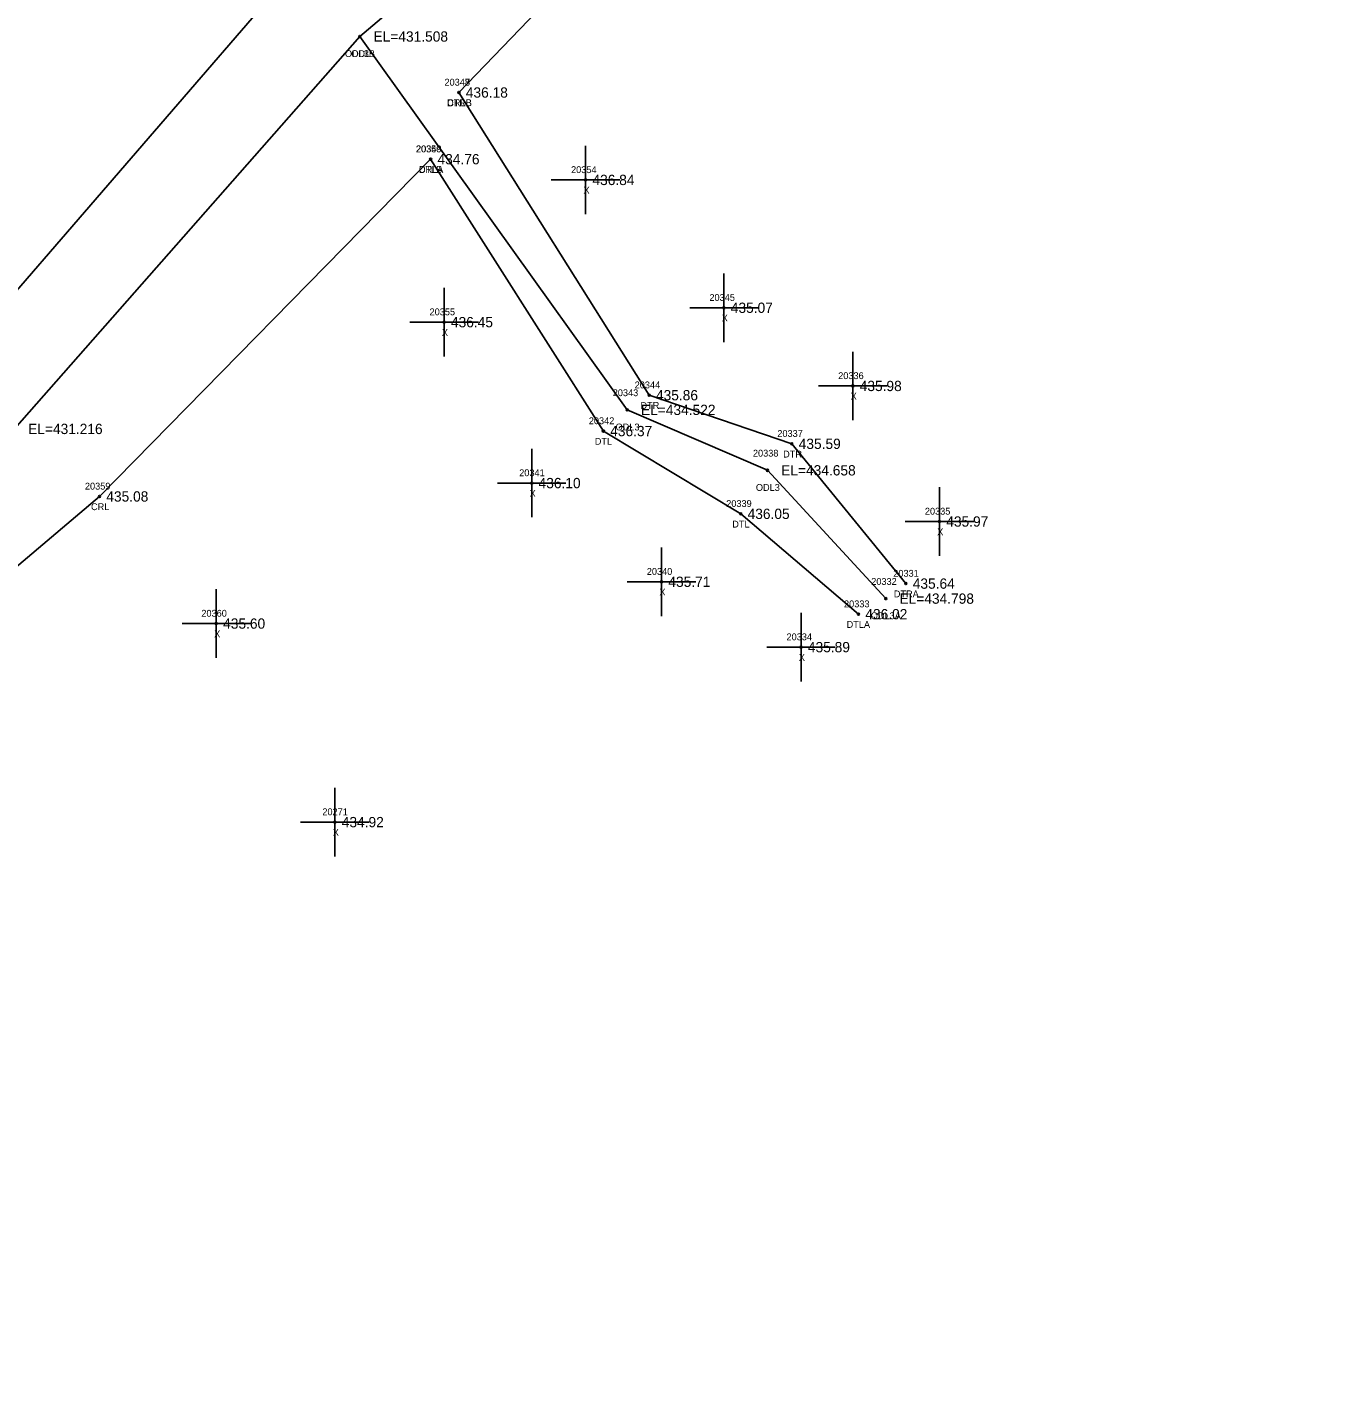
# Model space of a CAD drawing. Extents: x 1797709 to 1799052, y 896018 to 896955.
# Drawn here: x 1798186.8 to 1798378.7, y 896130.7 to 896328.3 of the extents above; entities that cross this region are included whole.
import ezdxf

# ---------------------------------------------------------------- set-up
doc = ezdxf.new("R2010")
doc.units = 0
for name, color, linetype in [('RD_EX_H2O', 7, 'Continuous'), ('RD_EX_H2O_txCode', 7, 'Continuous'), ('RD_EX_Misc', 7, 'Continuous'), ('RD_EX_Misc_txCode', 7, 'Continuous'), ('RD_EX_TX_H2O_ELEV', 7, 'Continuous'), ('RD_EX_TX_Misc_ELEV', 7, 'Continuous'), ('RD_SMD_Locator', 7, 'Continuous')]:
    doc.layers.add(name, color=color, linetype=linetype)

msp = doc.modelspace()

# ---------------------------------------------------------------- linework, layer by layer
at = {"layer": 'RD_EX_H2O'}
for points in [[(1798652.43, 896917.58), (1798601.94, 896827.15), (1798558.78, 896718.92), (1798516.66, 896628.32), (1798463.08, 896540.21), (1798439.21, 896521.86), (1798389.85, 896497.35), (1798369.72, 896471.55), (1798343.52, 896433.35), (1798291.39, 896374.31), (1798235.39, 896326.89), (1798184.99, 896269.63), (1798095.18, 896198.01), (1798023.89, 896139.85)], [(1798502.61, 896635.66), (1798452.16, 896551.79), (1798380.86, 896504.02), (1798360.17, 896479.84), (1798335.44, 896438.68), (1798277.37, 896387.2), (1798228.36, 896339.61), (1798175.66, 896278.7), (1798083.83, 896204.11), (1798020.11, 896146.19)], [(1798443.56, 896510.19), (1798406.44, 896491.18), (1798387.57, 896460.96), (1798358.05, 896423.51), (1798298.17, 896368.97), (1798249.86, 896318.72)], [(1798312.14, 896244.87), (1798294.88, 896263.59), (1798274.42, 896272.41), (1798235.39, 896326.89)], [(1798315.08, 896247.06), (1798298.44, 896267.46), (1798277.61, 896274.55), (1798249.86, 896318.72)], [(1798245.73, 896308.99), (1798197.4, 896259.78), (1798112.74, 896188.08), (1798043.49, 896130.72)], [(1798308.16, 896242.6), (1798290.98, 896257.24), (1798270.93, 896269.32), (1798245.73, 896308.99)]]:
    msp.add_lwpolyline(points, dxfattribs=at)
at = {"layer": 'RD_EX_Misc'}
for p, q in [((1798268.34, 896300.96), (1798268.34, 896310.96)), ((1798263.34, 896305.96), (1798273.34, 896305.96)), ((1798288.53, 896282.31), (1798288.53, 896292.31)), ((1798247.69, 896280.21), (1798247.69, 896290.21)), ((1798283.53, 896287.31), (1798293.53, 896287.31)), ((1798242.69, 896285.21), (1798252.69, 896285.21)), ((1798307.34, 896270.9), (1798307.34, 896280.9)), ((1798302.34, 896275.9), (1798312.34, 896275.9)), ((1798260.48, 896256.73), (1798260.48, 896266.73)), ((1798255.48, 896261.73), (1798265.48, 896261.73)), ((1798319.97, 896251.12), (1798319.97, 896261.12)), ((1798314.97, 896256.12), (1798324.97, 896256.12)), ((1798279.42, 896242.33), (1798279.42, 896252.33)), ((1798214.45, 896236.23), (1798214.45, 896246.23)), ((1798274.42, 896247.33), (1798284.42, 896247.33)), ((1798299.78, 896232.79), (1798299.78, 896242.79)), ((1798209.45, 896241.23), (1798219.45, 896241.23)), ((1798294.78, 896237.79), (1798304.78, 896237.79)), ((1798231.76, 896207.26), (1798231.76, 896217.26)), ((1798226.76, 896212.26), (1798236.76, 896212.26))]:
    msp.add_line(p, q, dxfattribs=at)
at = {"layer": 'RD_SMD_Locator'}
for centre in [(1798235.39, 896326.89), (1798235.39, 896326.89), (1798249.86, 896318.72), (1798249.86, 896318.72), (1798245.73, 896308.99), (1798245.73, 896308.99), (1798268.34, 896305.96), (1798288.53, 896287.31), (1798247.69, 896285.21), (1798307.34, 896275.9), (1798277.61, 896274.55), (1798274.42, 896272.41), (1798270.93, 896269.32), (1798298.44, 896267.46), (1798294.88, 896263.59), (1798260.48, 896261.73), (1798197.4, 896259.78), (1798290.98, 896257.24), (1798319.97, 896256.12), (1798279.42, 896247.33), (1798315.08, 896247.06), (1798312.14, 896244.87), (1798308.16, 896242.6), (1798214.45, 896241.23), (1798299.78, 896237.79), (1798231.76, 896212.26)]:
    msp.add_circle(centre, 0.15, dxfattribs=at)

# ---------------------------------------------------------------- texts
at = {"layer": 'RD_EX_H2O_txCode'}
for s, p in [('ODL3B', (1798233.22, 896323.89)), ('ODL', (1798234.14, 896323.89)), ('20347', (1798247.75, 896319.72)), ('20348', (1798247.75, 896319.72)), ('CRLB', (1798248.16, 896316.72)), ('DTRB', (1798248.12, 896316.72)), ('20350', (1798243.57, 896309.99)), ('20349', (1798243.61, 896309.99)), ('CRLA', (1798244.01, 896306.99)), ('DTLB', (1798244.01, 896306.99)), ('20344', (1798275.5, 896275.55)), ('20343', (1798272.3, 896274.41)), ('DTR', (1798276.35, 896272.55)), ('20342', (1798268.81, 896270.32)), ('ODL3', (1798272.72, 896269.41)), ('DTL', (1798269.68, 896267.32)), ('20337', (1798296.32, 896268.46)), ('20338', (1798292.76, 896265.59)), ('DTR', (1798297.17, 896265.46)), ('20359', (1798195.28, 896260.78)), ('ODL3', (1798293.19, 896260.59)), ('CRL', (1798196.17, 896257.78)), ('20339', (1798288.86, 896258.24)), ('DTL', (1798289.74, 896255.24)), ('20332', (1798310.02, 896246.87)), ('20331', (1798313.24, 896248.06)), ('DTRA', (1798313.32, 896245.06)), ('20333', (1798306.05, 896243.6)), ('ODL3A', (1798309.96, 896241.87)), ('DTLA', (1798306.43, 896240.6))]:
    msp.add_text(s, height=1, dxfattribs=at).set_placement(p)
at = {"layer": 'RD_EX_Misc_txCode'}
for s, p in [('20354', (1798266.22, 896306.96)), ('X', (1798268.03, 896303.96)), ('20345', (1798286.41, 896288.31)), ('20355', (1798245.57, 896286.21)), ('X', (1798288.21, 896285.31)), ('X', (1798247.37, 896283.21)), ('20336', (1798305.2, 896276.9)), ('X', (1798307.02, 896273.9)), ('20341', (1798258.65, 896262.73)), ('X', (1798260.17, 896259.73)), ('20335', (1798317.85, 896257.12)), ('X', (1798319.65, 896254.12)), ('20340', (1798277.27, 896248.33)), ('X', (1798279.11, 896245.33)), ('20360', (1798212.27, 896242.23)), ('X', (1798214.14, 896239.23)), ('20334', (1798297.66, 896238.79)), ('X', (1798299.46, 896235.79)), ('20271', (1798229.93, 896213.26)), ('X', (1798231.45, 896210.26))]:
    msp.add_text(s, height=1, dxfattribs=at).set_placement(p)
at = {"layer": 'RD_EX_TX_H2O_ELEV'}
for s, p in [('EL=431.508', (1798237.39, 896326.14)), ('EL=431.508', (1798237.39, 896326.14)), ('436.18', (1798250.86, 896317.97)), ('436.18', (1798250.86, 896317.97)), ('434.76', (1798246.73, 896308.24)), ('434.76', (1798246.73, 896308.24)), ('435.86', (1798278.61, 896273.8)), ('EL=434.522', (1798276.42, 896271.66)), ('EL=431.216', (1798186.99, 896268.88)), ('436.37', (1798271.93, 896268.57)), ('435.59', (1798299.44, 896266.71)), ('EL=434.658', (1798296.88, 896262.84)), ('435.08', (1798198.4, 896259.03)), ('436.05', (1798291.98, 896256.49)), ('435.64', (1798316.08, 896246.31)), ('EL=434.798', (1798314.14, 896244.12)), ('436.02', (1798309.16, 896241.85))]:
    msp.add_text(s, height=1.5, dxfattribs=at).set_placement(p)
at = {"layer": 'RD_EX_TX_Misc_ELEV'}
for s, p in [('436.84', (1798269.34, 896305.21)), ('435.07', (1798289.53, 896286.56)), ('436.45', (1798248.69, 896284.46)), ('435.98', (1798308.34, 896275.15)), ('436.10', (1798261.48, 896260.98)), ('435.97', (1798320.97, 896255.37)), ('435.71', (1798280.42, 896246.58)), ('435.60', (1798215.45, 896240.48)), ('435.89', (1798300.78, 896237.04)), ('434.92', (1798232.76, 896211.51))]:
    msp.add_text(s, height=1.5, dxfattribs=at).set_placement(p)

doc.saveas('drawing.dxf')
